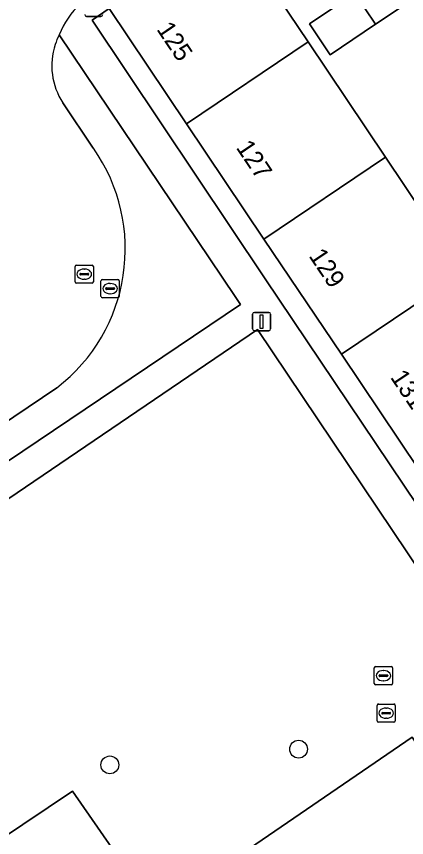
# Model space of a CAD drawing. Extents: x 158793 to 159888, y 384317 to 385256.
# Drawn here: x 159171.61 to 159193.03, y 384582.61 to 384627.65 of the extents above; entities that cross this region are included whole.
import ezdxf

# ---------------------------------------------------------------- set-up
doc = ezdxf.new("R2010")
doc.units = 0
for name, color, linetype in [('IMGEO_Boom', 7, 'Continuous'), ('IMGEO_Erf', 7, 'Continuous'), ('IMGEO_Groenvoorziening', 7, 'Continuous'), ('IMGEO_Lichtmast', 7, 'Continuous'), ('IMGEO_Pand', 7, 'Continuous'), ('IMGEO_Pand_nummerreeks', 7, 'Continuous'), ('IMGEO_Rijbaan_lokaal_open', 7, 'Continuous'), ('IMGEO_Rioolput', 7, 'Continuous'), ('IMGEO_Voetpad_gesloten', 7, 'Continuous'), ('IMGEO_Voetpad_open', 7, 'Continuous')]:
    doc.layers.add(name, color=color, linetype=linetype)

msp = doc.modelspace()

# ---------------------------------------------------------------- linework, layer by layer
at = {"layer": 'IMGEO_Boom'}
for centre in [(159187.102, 384587.457), (159176.741, 384586.594)]:
    msp.add_circle(centre, 0.489, dxfattribs=at)
at = {"layer": 'IMGEO_Erf'}
for points in [[(159189.5, 384636.563), (159183.38, 384632.567), (159187.63, 384626.246), (159191.879, 384619.926), (159196.129, 384613.605), (159200.378, 384607.285), (159204.628, 384600.965), (159208.877, 384594.644), (159214.996, 384598.764)], [(159191.334, 384627.231), (159188.834, 384625.549), (159187.7, 384627.236), (159190.199, 384628.918), (159192.698, 384630.6), (159193.834, 384628.912)]]:
    msp.add_lwpolyline(points, close=True, dxfattribs=at)
at = {"layer": 'IMGEO_Groenvoorziening'}
for points in [[(159183.92, 384611.847), (159183.625, 384612.286), (159173.958, 384626.637)], [(159174.154, 384622.915), (159175.833, 384620.417)], [(159173.826, 384607.279), (159167.457, 384602.991), (159168.528, 384601.493), (159183.92, 384611.847)]]:
    msp.add_lwpolyline(points, dxfattribs=at)
msp.add_lwpolyline([(159184.844, 384610.474), (159149.937, 384586.778), (159139.375, 384579.667), (159141.123, 384576.932), (159150.625, 384583.433), (159151.747, 384581.759), (159165.041, 384590.724), (159170.605, 384582.437), (159174.689, 384585.159), (159179.297, 384578.512), (159193.347, 384588.107), (159197.808, 384581.483), (159198.988, 384582.307), (159199.249, 384581.925), (159200.917, 384582.98), (159201.158, 384582.618), (159202.847, 384583.73), (159200.329, 384587.446), (159199.667, 384588.43)], close=True, dxfattribs=at)
for centre, radius, start, end in [((159177.376, 384624.905), 3.832, 153.129, 161.7987), ((159177.289, 384624.947), 3.736, 161.9917, 212.9526), ((159168, 384614.891), 9.586, 307.4294, 35.1996)]:
    msp.add_arc(centre, radius, start, end, dxfattribs=at)
at = {"layer": 'IMGEO_Lichtmast'}
for p, q in [((159176.248, 384627.648), (159175.458, 384627.648)), ((159175.458, 384627.648), (159176.248, 384627.648)), ((159184.674, 384611.411), (159185.464, 384611.411)), ((159185.464, 384611.411), (159184.674, 384611.411)), ((159184.574, 384610.511), (159184.574, 384611.311)), ((159184.574, 384611.311), (159184.574, 384610.511)), ((159185.564, 384611.311), (159185.564, 384610.511)), ((159185.564, 384610.511), (159185.564, 384611.311)), ((159185.464, 384610.411), (159184.674, 384610.411)), ((159184.674, 384610.411), (159185.464, 384610.411))]:
    msp.add_line(p, q, dxfattribs=at)
msp.add_lwpolyline([(159184.994, 384611.286), (159185.144, 384611.286), (159185.144, 384610.536), (159184.994, 384610.536), (159184.994, 384611.286)], dxfattribs=at)
for centre, start, end in [((159175.458, 384627.748), 180, 270), ((159175.458, 384627.748), 180, 270), ((159176.248, 384627.748), 270, 0), ((159176.248, 384627.748), 270, 0), ((159184.674, 384611.311), 90, 180), ((159184.674, 384611.311), 90, 180), ((159185.464, 384611.311), 0, 90), ((159185.464, 384611.311), 360, 90), ((159184.674, 384610.511), 180, 270), ((159184.674, 384610.511), 180, 270), ((159185.464, 384610.511), 270, 0), ((159185.464, 384610.511), 270, 0)]:
    msp.add_arc(centre, 0.1, start, end, dxfattribs=at)
at = {"layer": 'IMGEO_Pand'}
for points in [[(159183.38, 384632.567), (159176.706, 384628.077), (159180.954, 384621.758), (159187.63, 384626.246)], [(159193.834, 384628.912), (159192.698, 384630.6), (159190.199, 384628.918), (159191.334, 384627.231)], [(159190.199, 384628.918), (159187.7, 384627.236), (159188.834, 384625.549), (159191.334, 384627.231)], [(159187.63, 384626.246), (159180.954, 384621.758), (159185.203, 384615.437), (159191.879, 384619.926)], [(159191.879, 384619.926), (159185.203, 384615.437), (159189.452, 384609.117), (159196.129, 384613.605)], [(159196.129, 384613.605), (159189.452, 384609.117), (159193.701, 384602.796), (159200.378, 384607.285)]]:
    msp.add_lwpolyline(points, close=True, dxfattribs=at)
at = {"layer": 'IMGEO_Rijbaan_lokaal_open'}
for points in [[(159175.833, 384620.417), (159174.154, 384622.915)], [(159140.653, 384591.012), (159130.548, 384584.195), (159119.566, 384576.775), (159122.32, 384572.583), (159144.836, 384587.745), (159146.744, 384589.03), (159161.991, 384599.309), (159164.688, 384601.127), (159167.457, 384602.991), (159173.826, 384607.279)]]:
    msp.add_lwpolyline(points, dxfattribs=at)
for centre, radius, start, end in [((159178.485, 384624.823), 4.877, 133.5808, 158.1667), ((159177.376, 384624.905), 3.832, 153.129, 161.7987), ((159177.289, 384624.947), 3.736, 161.9917, 212.9526), ((159168, 384614.891), 9.586, 307.4294, 35.1996)]:
    msp.add_arc(centre, radius, start, end, dxfattribs=at)
at = {"layer": 'IMGEO_Rioolput'}
for p, q in [((159174.835, 384613.083), (159174.835, 384613.935)), ((159174.91, 384614.009), (159175.762, 384614.009)), ((159175.323, 384613.789), (159175.348, 384613.789)), ((159175.836, 384613.935), (159175.836, 384613.083)), ((159175.094, 384613.503), (159175.094, 384613.515)), ((159175.532, 384613.466), (159175.134, 384613.466)), ((159175.137, 384613.552), (159175.535, 384613.552)), ((159175.346, 384613.229), (159175.321, 384613.229)), ((159175.578, 384613.515), (159175.578, 384613.503)), ((159176.329, 384613.22), (159177.181, 384613.22)), ((159175.762, 384613.009), (159174.91, 384613.009)), ((159176.254, 384612.294), (159176.254, 384613.146)), ((159176.556, 384612.763), (159176.954, 384612.763)), ((159176.742, 384613), (159176.767, 384613)), ((159177.255, 384613.146), (159177.255, 384612.294)), ((159176.513, 384612.714), (159176.513, 384612.726)), ((159176.951, 384612.677), (159176.553, 384612.677)), ((159176.765, 384612.44), (159176.74, 384612.44)), ((159176.997, 384612.726), (159176.997, 384612.714)), ((159177.181, 384612.22), (159176.329, 384612.22)), ((159191.259, 384591.064), (159191.259, 384591.916)), ((159191.334, 384591.99), (159192.186, 384591.99)), ((159191.747, 384591.77), (159191.772, 384591.77)), ((159192.26, 384591.916), (159192.26, 384591.064)), ((159191.518, 384591.484), (159191.518, 384591.496)), ((159191.956, 384591.447), (159191.558, 384591.447)), ((159191.561, 384591.533), (159191.959, 384591.533)), ((159191.77, 384591.21), (159191.745, 384591.21)), ((159192.002, 384591.496), (159192.002, 384591.484)), ((159192.186, 384590.99), (159191.334, 384590.99)), ((159191.41, 384589.008), (159191.41, 384589.86)), ((159191.485, 384589.934), (159192.337, 384589.934)), ((159192.411, 384589.86), (159192.411, 384589.008)), ((159191.669, 384589.428), (159191.669, 384589.44)), ((159192.107, 384589.391), (159191.709, 384589.391)), ((159191.712, 384589.477), (159192.11, 384589.477)), ((159191.898, 384589.714), (159191.923, 384589.714)), ((159192.153, 384589.44), (159192.153, 384589.428)), ((159192.337, 384588.934), (159191.485, 384588.934)), ((159191.921, 384589.154), (159191.896, 384589.154))]:
    msp.add_line(p, q, dxfattribs=at)
for points in [[(159174.835, 384613.083), (159174.835, 384613.935)], [(159174.91, 384614.009), (159175.762, 384614.009)], [(159175.836, 384613.935), (159175.836, 384613.083)], [(159176.329, 384613.22), (159177.181, 384613.22)], [(159175.762, 384613.009), (159174.91, 384613.009)], [(159176.254, 384612.294), (159176.254, 384613.146)], [(159177.255, 384613.146), (159177.255, 384612.294)], [(159177.181, 384612.22), (159176.329, 384612.22)], [(159191.259, 384591.064), (159191.259, 384591.916)], [(159191.334, 384591.99), (159192.186, 384591.99)], [(159192.26, 384591.916), (159192.26, 384591.064)], [(159192.186, 384590.99), (159191.334, 384590.99)], [(159191.41, 384589.008), (159191.41, 384589.86)], [(159191.485, 384589.934), (159192.337, 384589.934)], [(159192.411, 384589.86), (159192.411, 384589.008)], [(159192.337, 384588.934), (159191.485, 384588.934)]]:
    msp.add_lwpolyline(points, dxfattribs=at)
for centre, radius, start, end in [((159174.912, 384613.933), 0.0765, 91.552, 178.448), ((159174.912, 384613.933), 0.0765, 91.552, 178.448), ((159175.76, 384613.933), 0.0765, 1.552, 88.448), ((159175.76, 384613.933), 0.0765, 1.552, 88.448), ((159175.134, 384613.512), 0.0403, 85.8775, 175.7526), ((159175.131, 384613.502), 0.0366, 178.938, 274.7102), ((159175.535, 384613.509), 0.043, 264.8664, 352.4533), ((159175.539, 384613.514), 0.0386, 1.7309, 96.639), ((159176.331, 384613.144), 0.0765, 91.552, 178.448), ((159176.331, 384613.144), 0.0765, 91.552, 178.448), ((159177.179, 384613.144), 0.0765, 1.552, 88.448), ((159177.179, 384613.144), 0.0765, 1.552, 88.448), ((159174.912, 384613.085), 0.0765, 181.552, 268.448), ((159174.912, 384613.085), 0.0765, 181.552, 268.448), ((159175.76, 384613.085), 0.0765, 271.552, 358.448), ((159175.76, 384613.085), 0.0765, 271.552, 358.448), ((159176.553, 384612.723), 0.0403, 85.8775, 175.7526), ((159176.958, 384612.725), 0.0386, 1.7309, 96.639), ((159176.55, 384612.713), 0.0366, 178.938, 274.7102), ((159176.954, 384612.72), 0.043, 264.8664, 352.4533), ((159176.331, 384612.296), 0.0765, 181.552, 268.448), ((159176.331, 384612.296), 0.0765, 181.552, 268.448), ((159177.179, 384612.296), 0.0765, 271.552, 358.448), ((159177.179, 384612.296), 0.0765, 271.552, 358.448), ((159191.336, 384591.914), 0.0765, 91.552, 178.448), ((159191.336, 384591.914), 0.0765, 91.552, 178.448), ((159192.184, 384591.914), 0.0765, 1.552, 88.448), ((159192.184, 384591.914), 0.0765, 1.552, 88.448), ((159191.558, 384591.493), 0.0403, 85.8775, 175.7526), ((159191.555, 384591.483), 0.0366, 178.938, 274.7102), ((159191.959, 384591.49), 0.043, 264.8664, 352.4533), ((159191.963, 384591.495), 0.0386, 1.7309, 96.639), ((159191.336, 384591.066), 0.0765, 181.552, 268.448), ((159191.336, 384591.066), 0.0765, 181.552, 268.448), ((159192.184, 384591.066), 0.0765, 271.552, 358.448), ((159192.184, 384591.066), 0.0765, 271.552, 358.448), ((159191.487, 384589.858), 0.0765, 91.552, 178.448), ((159191.487, 384589.858), 0.0765, 91.552, 178.448), ((159192.335, 384589.858), 0.0765, 1.552, 88.448), ((159192.335, 384589.858), 0.0765, 1.552, 88.448), ((159191.709, 384589.437), 0.0403, 85.8775, 175.7526), ((159191.706, 384589.427), 0.0366, 178.938, 274.7102), ((159192.11, 384589.434), 0.043, 264.8664, 352.4533), ((159192.114, 384589.439), 0.0386, 1.7309, 96.639), ((159191.487, 384589.01), 0.0765, 181.552, 268.448), ((159191.487, 384589.01), 0.0765, 181.552, 268.448), ((159192.335, 384589.01), 0.0765, 271.552, 358.448), ((159192.335, 384589.01), 0.0765, 271.552, 358.448)]:
    msp.add_arc(centre, radius, start, end, dxfattribs=at)
for centre, major_axis, ratio, start_param, end_param in [((159175.322, 384613.509), (-0.387, 0.002), 0.722429, 4.712389, 7.853982), ((159175.347, 384613.509), (-0.39, 0.002), 0.717154, 1.570796, 4.712389), ((159176.741, 384612.72), (-0.387, 0.002), 0.722429, 4.712389, 7.853982), ((159176.766, 384612.72), (-0.39, 0.002), 0.717154, 1.570796, 4.712389), ((159191.746, 384591.49), (-0.387, 0.002), 0.722429, 4.712389, 7.853982), ((159191.771, 384591.49), (-0.39, 0.002), 0.717154, 1.570796, 4.712389), ((159191.897, 384589.434), (-0.387, 0.002), 0.722429, 4.712389, 7.853982), ((159191.922, 384589.434), (-0.39, 0.002), 0.717154, 1.570796, 4.712389)]:
    msp.add_ellipse(centre, major_axis=major_axis, ratio=ratio, start_param=start_param, end_param=end_param, dxfattribs=at)
at = {"layer": 'IMGEO_Voetpad_gesloten'}
msp.add_lwpolyline([(159197.808, 384581.483), (159193.347, 384588.107), (159179.297, 384578.512), (159174.689, 384585.159), (159170.605, 384582.437), (159165.041, 384590.724), (159151.747, 384581.759), (159150.625, 384583.433), (159141.123, 384576.932)], dxfattribs=at)
at = {"layer": 'IMGEO_Voetpad_open'}
for points in [[(159184.844, 384610.474), (159199.667, 384588.43), (159201.24, 384589.496), (159185.263, 384613.249), (159175.767, 384627.444), (159176.706, 384628.077), (159176.084, 384629.066)], [(159173.958, 384626.637), (159183.625, 384612.286), (159183.92, 384611.847), (159168.528, 384601.493), (159162.998, 384597.735), (159162.234, 384597.236), (159147.745, 384587.587), (159146.744, 384589.03), (159144.836, 384587.745), (159145.803, 384586.282), (159138.32, 384581.256), (159138.377, 384581.17), (159139.375, 384579.667), (159149.937, 384586.778), (159184.844, 384610.474)]]:
    msp.add_lwpolyline(points, dxfattribs=at)
msp.add_lwpolyline([(159189.452, 384609.117), (159185.203, 384615.437), (159180.954, 384621.758), (159176.706, 384628.077), (159175.767, 384627.444), (159185.263, 384613.249), (159201.24, 384589.496), (159202.203, 384590.149), (159197.95, 384596.475), (159193.701, 384602.796)], close=True, dxfattribs=at)
msp.add_arc((159178.485, 384624.823), 4.877, 133.5808, 158.1667, dxfattribs=at)

# ---------------------------------------------------------------- texts
at = {"layer": 'IMGEO_Pand_nummerreeks'}
for s, p in [('125', (159179.275, 384626.944)), ('127', (159183.638, 384620.454)), ('129', (159187.634, 384614.51)), ('131', (159192.108, 384607.855))]:
    msp.add_text(s, height=1, rotation=303.9132, dxfattribs=at).set_placement(p)

doc.saveas('drawing.dxf')
